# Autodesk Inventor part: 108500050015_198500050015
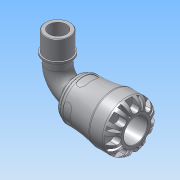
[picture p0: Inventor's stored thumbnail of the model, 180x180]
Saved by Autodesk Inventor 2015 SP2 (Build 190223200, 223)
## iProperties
Created: 2016-12
Part Number: 108500050015_198500050015
Material: PVC-Piping
Description: PLASSON 90° ELBOW WITH THREADED MALE OFFTAKE 50X1.1/2" SERIES 1
Document SubType Name: Modeling
Designer: KIM
Mass: 664.223 g
Surface Area: 733.008 cm^2
Volume: 474.445 cm^3
Density: 1.4 g/cm^3
Appearance: Smooth - White
Author: KIM
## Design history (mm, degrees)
derived "1085.ipt"
feature "Solid1::1085.ipt"
tag "TaggingFeature1"
body "Solid1"
other parameters: "d1" = 33.18, "d3" = 62.5, "d4" = 85, "d8" = 72.25, "d13" = 9, "d14" = 9, "d15" = 0, "d17" = 360 deg, "d19" = 8 deg, "d20" = 1, "d21" = 1, "d22" = 8 deg, "d24" = 0, "d26" = 360 deg, "d33" = 8.5, "d43" = 66.3, "d51" = 0.85, "d54" = 17.5, "d55" = 11, "d57" = 17.64, "d58" = 0, "d74" = 0, "d78" = 79, "d82" = 1, "d115" = 360 deg, "d207" = 90 deg, "d228" = 14.875, "d247" = 1.7, "d248" = 4.74, "d268" = 39.7375, "d269" = 4.74, "d270" = 122, "d276" = 47.803, "d277" = 21, "d278" = 52.5833, "d279" = 68, "d280" = 23.1, "d281" = 7.17045, "d283" = 43.0227, "d286" = 0, "d287" = 0, "d288" = 33.4621, "d290" = 11.63865, "d292" = 30 deg, "E_" = 85, "l_" = 79, "A_" = 122, "A_1" = 68, "l_2" = 21, "R_" = 47.803, "d9" = 11.25, "d11" = 85, "d12" = 62.5, "d289" = 33.4621
